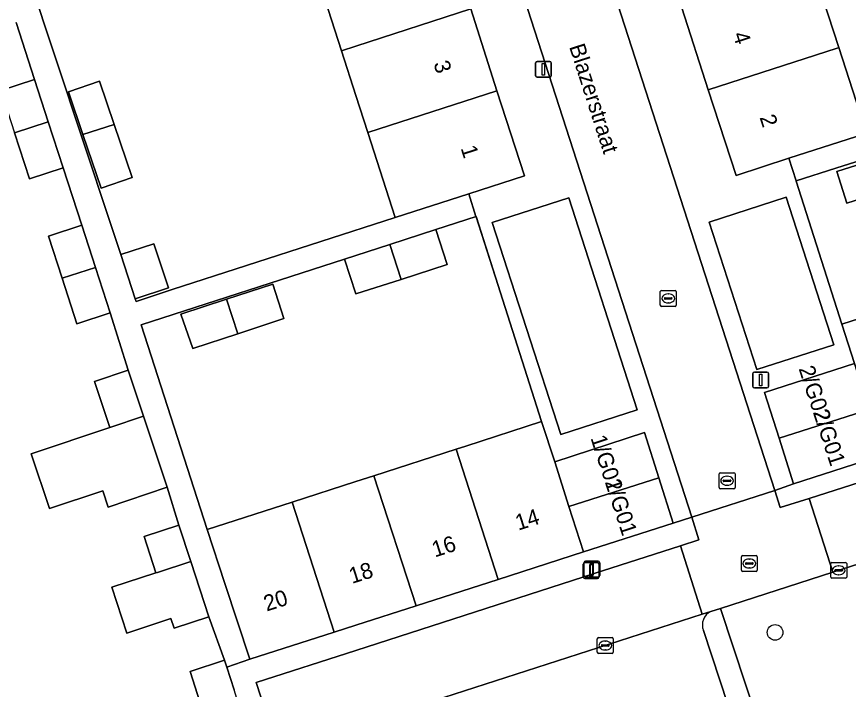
# Model space of a CAD drawing. Extents: x 159371 to 159986, y 382987 to 383597.
# Drawn here: x 159478.7 to 159530.9, y 383198.2 to 383240.4 of the extents above; entities that cross this region are included whole.
import ezdxf

# ---------------------------------------------------------------- set-up
doc = ezdxf.new("R2010")
doc.units = 0
for name, color, linetype in [('IMGEO_Boom', 7, 'Continuous'), ('IMGEO_Erf', 7, 'Continuous'), ('IMGEO_Groenvoorziening', 7, 'Continuous'), ('IMGEO_Kolk', 7, 'Continuous'), ('IMGEO_Lichtmast', 7, 'Continuous'), ('IMGEO_Muur', 7, 'Continuous'), ('IMGEO_Openbare_ruimte_label', 7, 'Continuous'), ('IMGEO_Pand', 7, 'Continuous'), ('IMGEO_Pand_nummerreeks', 7, 'Continuous'), ('IMGEO_Parkeervlak_open', 7, 'Continuous'), ('IMGEO_Rijbaan_lokaal_open', 7, 'Continuous'), ('IMGEO_Rioolput', 7, 'Continuous'), ('IMGEO_Voetpad_open', 7, 'Continuous')]:
    doc.layers.add(name, color=color, linetype=linetype)

msp = doc.modelspace()

# ---------------------------------------------------------------- linework, layer by layer
at = {"layer": 'IMGEO_Boom'}
msp.add_circle((159526.293, 383201.78), 0.489, dxfattribs=at)
at = {"layer": 'IMGEO_Erf'}
for points in [[(159531.284, 383283.727), (159529.246, 383283.829), (159519.728, 383280.725), (159521.455, 383275.325), (159518.605, 383274.414), (159520.255, 383269.333), (159521.919, 383264.211), (159523.611, 383259.001), (159525.285, 383253.847), (159526.535, 383250), (159526.957, 383248.702), (159528.622, 383243.576), (159530.29, 383238.439), (159532.035, 383233.068)], [(159474.303, 383258.392), (159484.606, 383227.42), (159485.248, 383225.462), (159487.33, 383226.144), (159488.238, 383223.375), (159486.157, 383222.692), (159486.209, 383222.532), (159488.475, 383223.275), (159502.462, 383227.783), (159500.748, 383233.11), (159500, 383235.437), (159499.1, 383238.237), (159497.445, 383243.381), (159495.793, 383248.517), (159495.316, 383250), (159494.126, 383253.699), (159492.462, 383258.873), (159488.591, 383257.619), (159486.93, 383262.784), (159490.801, 383264.037), (159489.146, 383269.183), (159485.21, 383267.909), (159483.482, 383273.28), (159466.224, 383267.732)], [(159477.72, 383235.751), (159479.834, 383236.442), (159478.696, 383240.003)], [(159490.525, 383196.453), (159489.601, 383199.327), (159491.758, 383200.033), (159490.78, 383202.765), (159488.592, 383202.046), (159488.395, 383202.646), (159485.637, 383201.74), (159484.695, 383204.606), (159487.453, 383205.513), (159486.706, 383207.787), (159488.894, 383208.506), (159488.161, 383210.876), (159484.461, 383209.638), (159484.12, 383210.655), (159480.784, 383209.538), (159479.633, 383212.974), (159484.57, 383214.627), (159483.604, 383217.513), (159485.703, 383218.216), (159484.587, 383221.813), (159482.497, 383221.131), (159481.567, 383223.976), (159480.704, 383226.615), (159482.795, 383227.299), (159481.642, 383230.906), (159479.529, 383230.216), (159478.586, 383233.1)]]:
    msp.add_lwpolyline(points, dxfattribs=at)
for points in [[(159561.744, 383231.135), (159558.829, 383240.129), (159535.859, 383232.707), (159532.941, 383231.781), (159530.104, 383230.88), (159527.615, 383230.086), (159527.624, 383230.058), (159530.484, 383221.094), (159535.245, 383222.623), (159535.829, 383222.811), (159541.002, 383224.472), (159546.128, 383226.119), (159551.293, 383227.778), (159556.447, 383229.434)], [(159485.967, 383230.29), (159484.01, 383229.627), (159482.871, 383232.987), (159481.96, 383235.674), (159483.917, 383236.337), (159484.837, 383233.623)], [(159530.8, 383228.688), (159530.169, 383230.674), (159533.007, 383231.575), (159535.925, 383232.502), (159536.566, 383230.519), (159533.646, 383229.592)], [(159507.534, 383227.84), (159505.016, 383227.034), (159505.723, 383224.846), (159502.835, 383223.911), (159500, 383222.994), (159499.277, 383225.177), (159486.536, 383221.053), (159490.664, 383208.234), (159495.999, 383209.952), (159500, 383211.241), (159501.129, 383211.604), (159506.286, 383213.265), (159506.889, 383213.459), (159511.648, 383214.991)], [(159491.878, 383222.663), (159494.778, 383223.614), (159495.481, 383221.446), (159492.581, 383220.495), (159489.763, 383219.571), (159489.015, 383221.724)]]:
    msp.add_lwpolyline(points, close=True, dxfattribs=at)
at = {"layer": 'IMGEO_Groenvoorziening'}
msp.add_lwpolyline([(159540.074, 383208.824), (159529.915, 383205.553), (159522.871, 383203.285), (159524.456, 383198.471), (159526.041, 383193.657), (159534.778, 383196.457), (159541.549, 383198.628), (159543.216, 383199.162), (159541.645, 383203.993)], close=True, dxfattribs=at)
at = {"layer": 'IMGEO_Kolk'}
for p, q in [((159519.095, 383222.288), (159519.095, 383223.14)), ((159519.17, 383223.214), (159520.022, 383223.214)), ((159519.583, 383222.994), (159519.608, 383222.994)), ((159520.096, 383223.14), (159520.096, 383222.288)), ((159519.354, 383222.708), (159519.354, 383222.72)), ((159519.792, 383222.671), (159519.394, 383222.671)), ((159519.397, 383222.757), (159519.795, 383222.757)), ((159519.838, 383222.72), (159519.838, 383222.708)), ((159520.022, 383222.214), (159519.17, 383222.214)), ((159519.606, 383222.434), (159519.581, 383222.434)), ((159522.783, 383210.86), (159522.783, 383211.712)), ((159522.858, 383211.786), (159523.71, 383211.786)), ((159523.271, 383211.566), (159523.296, 383211.566)), ((159523.784, 383211.712), (159523.784, 383210.86)), ((159523.042, 383211.28), (159523.042, 383211.292)), ((159523.48, 383211.243), (159523.082, 383211.243)), ((159523.085, 383211.329), (159523.483, 383211.329)), ((159523.294, 383211.006), (159523.269, 383211.006)), ((159523.526, 383211.292), (159523.526, 383211.28)), ((159523.71, 383210.786), (159522.858, 383210.786)), ((159529.785, 383205.245), (159529.785, 383206.097)), ((159529.86, 383206.171), (159530.712, 383206.171)), ((159530.273, 383205.951), (159530.298, 383205.951)), ((159530.786, 383206.097), (159530.786, 383205.245)), ((159530.044, 383205.665), (159530.044, 383205.677)), ((159530.482, 383205.628), (159530.084, 383205.628)), ((159530.087, 383205.714), (159530.485, 383205.714)), ((159530.296, 383205.391), (159530.271, 383205.391)), ((159530.528, 383205.677), (159530.528, 383205.665)), ((159530.712, 383205.171), (159529.86, 383205.171)), ((159515.143, 383200.531), (159515.143, 383201.383)), ((159515.218, 383201.457), (159516.07, 383201.457)), ((159515.631, 383201.237), (159515.656, 383201.237)), ((159516.144, 383201.383), (159516.144, 383200.531)), ((159515.402, 383200.951), (159515.402, 383200.963)), ((159515.84, 383200.914), (159515.442, 383200.914)), ((159515.445, 383201), (159515.843, 383201)), ((159515.654, 383200.677), (159515.629, 383200.677)), ((159515.886, 383200.963), (159515.886, 383200.951)), ((159516.07, 383200.457), (159515.218, 383200.457))]:
    msp.add_line(p, q, dxfattribs=at)
for points in [[(159519.095, 383222.288), (159519.095, 383223.14)], [(159519.17, 383223.214), (159520.022, 383223.214)], [(159520.096, 383223.14), (159520.096, 383222.288)], [(159520.022, 383222.214), (159519.17, 383222.214)], [(159522.783, 383210.86), (159522.783, 383211.712)], [(159522.858, 383211.786), (159523.71, 383211.786)], [(159523.784, 383211.712), (159523.784, 383210.86)], [(159523.71, 383210.786), (159522.858, 383210.786)], [(159529.785, 383205.245), (159529.785, 383206.097)], [(159529.86, 383206.171), (159530.712, 383206.171)], [(159530.786, 383206.097), (159530.786, 383205.245)], [(159530.712, 383205.171), (159529.86, 383205.171)], [(159515.143, 383200.531), (159515.143, 383201.383)], [(159515.218, 383201.457), (159516.07, 383201.457)], [(159516.144, 383201.383), (159516.144, 383200.531)], [(159516.07, 383200.457), (159515.218, 383200.457)]]:
    msp.add_lwpolyline(points, dxfattribs=at)
for centre, radius, start, end in [((159519.172, 383223.138), 0.0765, 91.552, 178.448), ((159519.172, 383223.138), 0.0765, 91.552, 178.448), ((159520.02, 383223.138), 0.0765, 1.552, 88.448), ((159520.02, 383223.138), 0.0765, 1.552, 88.448), ((159519.394, 383222.717), 0.0403, 85.8775, 175.7526), ((159519.391, 383222.707), 0.0366, 178.938, 274.7102), ((159519.795, 383222.714), 0.043, 264.8664, 352.4533), ((159519.799, 383222.719), 0.0386, 1.7309, 96.639), ((159519.172, 383222.29), 0.0765, 181.552, 268.448), ((159519.172, 383222.29), 0.0765, 181.552, 268.448), ((159520.02, 383222.29), 0.0765, 271.552, 358.448), ((159520.02, 383222.29), 0.0765, 271.552, 358.448), ((159522.86, 383211.71), 0.0765, 91.552, 178.448), ((159522.86, 383211.71), 0.0765, 91.552, 178.448), ((159523.708, 383211.71), 0.0765, 1.552, 88.448), ((159523.708, 383211.71), 0.0765, 1.552, 88.448), ((159523.082, 383211.289), 0.0403, 85.8775, 175.7526), ((159523.079, 383211.279), 0.0366, 178.938, 274.7102), ((159523.483, 383211.286), 0.043, 264.8664, 352.4533), ((159523.487, 383211.291), 0.0386, 1.7309, 96.639), ((159522.86, 383210.862), 0.0765, 181.552, 268.448), ((159522.86, 383210.862), 0.0765, 181.552, 268.448), ((159523.708, 383210.862), 0.0765, 271.552, 358.448), ((159523.708, 383210.862), 0.0765, 271.552, 358.448), ((159529.862, 383206.095), 0.0765, 91.552, 178.448), ((159529.862, 383206.095), 0.0765, 91.552, 178.448), ((159530.71, 383206.095), 0.0765, 1.552, 88.448), ((159530.71, 383206.095), 0.0765, 1.552, 88.448), ((159529.862, 383205.247), 0.0765, 181.552, 268.448), ((159529.862, 383205.247), 0.0765, 181.552, 268.448), ((159530.084, 383205.674), 0.0403, 85.8775, 175.7526), ((159530.081, 383205.664), 0.0366, 178.938, 274.7102), ((159530.485, 383205.671), 0.043, 264.8664, 352.4533), ((159530.489, 383205.676), 0.0386, 1.7309, 96.639), ((159530.71, 383205.247), 0.0765, 271.552, 358.448), ((159530.71, 383205.247), 0.0765, 271.552, 358.448), ((159515.22, 383201.381), 0.0765, 91.552, 178.448), ((159515.22, 383201.381), 0.0765, 91.552, 178.448), ((159516.068, 383201.381), 0.0765, 1.552, 88.448), ((159516.068, 383201.381), 0.0765, 1.552, 88.448), ((159515.22, 383200.533), 0.0765, 181.552, 268.448), ((159515.22, 383200.533), 0.0765, 181.552, 268.448), ((159515.442, 383200.96), 0.0403, 85.8775, 175.7526), ((159515.439, 383200.95), 0.0366, 178.938, 274.7102), ((159515.843, 383200.957), 0.043, 264.8664, 352.4533), ((159515.847, 383200.962), 0.0386, 1.7309, 96.639), ((159516.068, 383200.533), 0.0765, 271.552, 358.448), ((159516.068, 383200.533), 0.0765, 271.552, 358.448)]:
    msp.add_arc(centre, radius, start, end, dxfattribs=at)
for centre, major_axis, ratio, start_param, end_param in [((159519.582, 383222.714), (-0.387, 0.002), 0.722429, 4.712389, 7.853982), ((159519.607, 383222.714), (-0.39, 0.002), 0.717154, 1.570796, 4.712389), ((159523.27, 383211.286), (-0.387, 0.002), 0.722429, 4.712389, 7.853982), ((159523.295, 383211.286), (-0.39, 0.002), 0.717154, 1.570796, 4.712389), ((159530.272, 383205.671), (-0.387, 0.002), 0.722429, 4.712389, 7.853982), ((159530.297, 383205.671), (-0.39, 0.002), 0.717154, 1.570796, 4.712389), ((159515.63, 383200.957), (-0.387, 0.002), 0.722429, 4.712389, 7.853982), ((159515.655, 383200.957), (-0.39, 0.002), 0.717154, 1.570796, 4.712389)]:
    msp.add_ellipse(centre, major_axis=major_axis, ratio=ratio, start_param=start_param, end_param=end_param, dxfattribs=at)
at = {"layer": 'IMGEO_Lichtmast'}
for p, q in [((159511.268, 383236.674), (159511.268, 383237.474)), ((159511.268, 383237.474), (159511.268, 383236.674)), ((159511.368, 383237.574), (159512.158, 383237.574)), ((159512.158, 383237.574), (159511.368, 383237.574)), ((159512.258, 383237.474), (159512.258, 383236.674)), ((159512.258, 383236.674), (159512.258, 383237.474)), ((159512.158, 383236.574), (159511.368, 383236.574)), ((159511.368, 383236.574), (159512.158, 383236.574)), ((159524.893, 383217.202), (159524.893, 383218.002)), ((159524.893, 383218.002), (159524.893, 383217.202)), ((159524.993, 383218.102), (159525.783, 383218.102)), ((159525.783, 383218.102), (159524.993, 383218.102)), ((159525.883, 383218.002), (159525.883, 383217.202)), ((159525.883, 383217.202), (159525.883, 383218.002)), ((159525.783, 383217.102), (159524.993, 383217.102)), ((159524.993, 383217.102), (159525.783, 383217.102)), ((159514.263, 383205.253), (159514.263, 383206.053)), ((159514.263, 383206.053), (159514.263, 383205.253)), ((159514.305, 383205.344), (159514.305, 383206.144)), ((159514.305, 383206.144), (159514.305, 383205.344)), ((159514.363, 383206.153), (159515.153, 383206.153)), ((159515.153, 383206.153), (159514.363, 383206.153)), ((159514.405, 383206.244), (159515.195, 383206.244)), ((159515.195, 383206.244), (159514.405, 383206.244)), ((159515.253, 383206.053), (159515.253, 383205.253)), ((159515.253, 383205.253), (159515.253, 383206.053)), ((159515.295, 383206.144), (159515.295, 383205.344)), ((159515.295, 383205.344), (159515.295, 383206.144)), ((159515.195, 383205.244), (159514.405, 383205.244)), ((159514.405, 383205.244), (159515.195, 383205.244)), ((159515.153, 383205.153), (159514.363, 383205.153)), ((159514.363, 383205.153), (159515.153, 383205.153))]:
    msp.add_line(p, q, dxfattribs=at)
for points in [[(159511.688, 383237.449), (159511.838, 383237.449), (159511.838, 383236.699), (159511.688, 383236.699), (159511.688, 383237.449)], [(159525.313, 383217.977), (159525.463, 383217.977), (159525.463, 383217.227), (159525.313, 383217.227), (159525.313, 383217.977)], [(159514.683, 383206.028), (159514.833, 383206.028), (159514.833, 383205.278), (159514.683, 383205.278), (159514.683, 383206.028)], [(159514.725, 383206.119), (159514.875, 383206.119), (159514.875, 383205.369), (159514.725, 383205.369), (159514.725, 383206.119)]]:
    msp.add_lwpolyline(points, dxfattribs=at)
for centre, start, end in [((159511.368, 383237.474), 90, 180), ((159511.368, 383237.474), 90, 180), ((159512.158, 383237.474), 0, 90), ((159512.158, 383237.474), 360, 90), ((159511.368, 383236.674), 180, 270), ((159511.368, 383236.674), 180, 270), ((159512.158, 383236.674), 270, 0), ((159512.158, 383236.674), 270, 0), ((159524.993, 383218.002), 90, 180), ((159524.993, 383218.002), 90, 180), ((159525.783, 383218.002), 0, 90), ((159525.783, 383218.002), 360, 90), ((159524.993, 383217.202), 180, 270), ((159524.993, 383217.202), 180, 270), ((159525.783, 383217.202), 270, 0), ((159525.783, 383217.202), 270, 0), ((159514.363, 383206.053), 90, 180), ((159514.363, 383206.053), 90, 180), ((159514.405, 383206.144), 90, 180), ((159514.405, 383206.144), 90, 180), ((159515.153, 383206.053), 0, 90), ((159515.153, 383206.053), 360, 90), ((159515.195, 383206.144), 0, 90), ((159515.195, 383206.144), 360, 90), ((159514.363, 383205.253), 180, 270), ((159514.363, 383205.253), 180, 270), ((159514.405, 383205.344), 180, 270), ((159514.405, 383205.344), 180, 270), ((159515.153, 383205.253), 270, 0), ((159515.153, 383205.253), 270, 0), ((159515.195, 383205.344), 270, 0), ((159515.195, 383205.344), 270, 0)]:
    msp.add_arc(centre, 0.1, start, end, dxfattribs=at)
at = {"layer": 'IMGEO_Muur'}
for points in [[(159527.624, 383230.058), (159530.484, 383221.094)], [(159507.531, 383227.848), (159511.648, 383214.991)]]:
    msp.add_lwpolyline(points, dxfattribs=at)
at = {"layer": 'IMGEO_Pand'}
for points in [[(159505.546, 383246.004), (159500, 383244.208), (159497.445, 383243.381), (159499.1, 383238.237), (159500, 383238.528), (159507.201, 383240.86)], [(159528.622, 383243.576), (159520.441, 383240.921), (159522.107, 383235.784), (159530.19, 383238.407), (159530.29, 383238.439)], [(159507.201, 383240.86), (159500, 383238.528), (159499.1, 383238.237), (159500, 383235.437), (159500.748, 383233.11), (159508.849, 383235.734)], [(159522.107, 383235.784), (159523.844, 383230.429), (159527.161, 383231.498), (159531.921, 383233.031), (159532.035, 383233.068), (159530.29, 383238.439), (159530.19, 383238.407)], [(159479.834, 383236.442), (159477.72, 383235.751), (159478.586, 383233.1), (159480.701, 383233.786)], [(159484.837, 383233.623), (159483.917, 383236.337), (159481.96, 383235.674), (159482.871, 383232.987)], [(159500.748, 383233.11), (159502.462, 383227.783), (159507.076, 383229.267), (159510.568, 383230.39), (159508.849, 383235.734)], [(159480.701, 383233.786), (159478.586, 383233.1), (159479.529, 383230.216), (159481.642, 383230.906)], [(159484.837, 383233.623), (159482.871, 383232.987), (159484.01, 383229.627), (159485.967, 383230.29)], [(159533.007, 383231.575), (159530.169, 383230.674), (159530.8, 383228.688), (159533.646, 383229.592)], [(159482.795, 383227.299), (159480.704, 383226.615), (159481.567, 383223.976), (159483.659, 383224.654)], [(159502.835, 383223.911), (159505.723, 383224.846), (159505.016, 383227.034), (159502.126, 383226.099)], [(159485.248, 383225.462), (159486.157, 383222.692), (159488.238, 383223.375), (159487.33, 383226.144)], [(159502.835, 383223.911), (159502.126, 383226.099), (159500, 383225.411), (159499.277, 383225.177), (159500, 383222.994)], [(159483.659, 383224.654), (159481.567, 383223.976), (159482.497, 383221.131), (159484.587, 383221.813)], [(159491.878, 383222.663), (159492.581, 383220.495), (159495.481, 383221.446), (159494.778, 383223.614)], [(159491.878, 383222.663), (159489.015, 383221.724), (159489.763, 383219.571), (159492.581, 383220.495)], [(159531.277, 383218.64), (159532.194, 383215.748), (159533.093, 383212.915), (159538.46, 383214.64), (159535.829, 383222.811), (159535.245, 383222.623), (159530.484, 383221.094)], [(159531.277, 383218.64), (159525.641, 383216.827), (159526.549, 383213.96), (159532.194, 383215.748)], [(159484.57, 383214.627), (159486.67, 383215.33), (159485.703, 383218.216), (159483.604, 383217.513)], [(159526.549, 383213.96), (159527.457, 383211.093), (159533.093, 383212.915), (159532.194, 383215.748)], [(159486.67, 383215.33), (159484.57, 383214.627), (159479.633, 383212.974), (159480.784, 383209.538), (159484.12, 383210.655), (159484.461, 383209.638), (159488.161, 383210.876)], [(159508.931, 383205.106), (159514.272, 383206.822), (159513.353, 383209.671), (159512.481, 383212.472), (159511.648, 383214.991), (159506.889, 383213.459), (159506.286, 383213.265)], [(159519, 383211.469), (159518.096, 383214.307), (159512.481, 383212.472), (159513.353, 383209.671)], [(159508.931, 383205.106), (159506.286, 383213.265), (159501.129, 383211.604), (159503.773, 383203.448)], [(159495.999, 383209.952), (159498.642, 383201.8), (159500, 383202.236), (159503.773, 383203.448), (159501.129, 383211.604), (159500, 383211.241)], [(159519, 383211.469), (159513.353, 383209.671), (159514.272, 383206.822), (159519.903, 383208.631)], [(159495.999, 383209.952), (159490.664, 383208.234), (159491.778, 383204.846), (159493.339, 383200.096), (159498.642, 383201.8)], [(159487.453, 383205.513), (159487.545, 383205.542), (159489.641, 383206.231), (159488.894, 383208.506), (159486.706, 383207.787)], [(159489.641, 383206.231), (159487.545, 383205.542), (159487.453, 383205.513), (159484.695, 383204.606), (159485.637, 383201.74), (159488.395, 383202.646), (159488.592, 383202.046), (159490.78, 383202.765)], [(159492.685, 383197.153), (159492.353, 383198.185), (159491.9, 383199.592), (159491.758, 383200.033), (159489.601, 383199.327), (159490.525, 383196.453)]]:
    msp.add_lwpolyline(points, close=True, dxfattribs=at)
at = {"layer": 'IMGEO_Parkeervlak_open'}
for points in [[(159512.855, 383214.184), (159517.648, 383215.74), (159513.361, 383229.025), (159508.555, 383227.471)], [(159525.147, 383218.255), (159529.979, 383219.803), (159526.996, 383229.056), (159522.162, 383227.492)]]:
    msp.add_lwpolyline(points, close=True, dxfattribs=at)
for points in [[(159522.265, 383203.09), (159521.723, 383202.915), (159502.276, 383196.654), (159505.416, 383187.046), (159525.324, 383193.428)], [(159524.356, 383194.142), (159521.805, 383201.89)]]:
    msp.add_lwpolyline(points, dxfattribs=at)
msp.add_arc((159522.662, 383202.25), 0.929, 115.2802, 202.7728, dxfattribs=at)
at = {"layer": 'IMGEO_Rijbaan_lokaal_open'}
for points in [[(159521.064, 383209.004), (159526.269, 383210.676), (159514.229, 383247.954), (159509.028, 383246.282)], [(159520.354, 383207.214), (159521.723, 383202.915), (159522.265, 383203.09), (159522.871, 383203.285), (159529.915, 383205.553), (159528.425, 383210.177), (159526.617, 383209.599), (159526.269, 383210.676), (159521.064, 383209.004), (159521.521, 383207.59)]]:
    msp.add_lwpolyline(points, close=True, dxfattribs=at)
for points in [[(159591.243, 383219.067), (159572.368, 383213.005), (159570.5, 383218.852), (159566.151, 383217.448), (159564.747, 383221.794), (159528.425, 383210.177), (159529.915, 383205.553), (159540.074, 383208.824), (159540.707, 383209.028), (159559.015, 383214.923), (159559.453, 383215.064)], [(159501.85, 383196.521), (159502.276, 383196.654), (159521.723, 383202.915), (159520.354, 383207.214), (159514.946, 383205.47), (159500, 383200.651), (159493.749, 383198.635), (159499.75, 383180.18), (159500, 383180.243), (159536.251, 383191.843), (159534.778, 383196.457), (159526.041, 383193.657), (159525.324, 383193.428), (159505.416, 383187.046), (159504.961, 383186.9)]]:
    msp.add_lwpolyline(points, dxfattribs=at)
at = {"layer": 'IMGEO_Rioolput'}
for p, q in [((159524.178, 383205.672), (159524.178, 383206.524)), ((159524.253, 383206.598), (159525.105, 383206.598)), ((159524.666, 383206.378), (159524.691, 383206.378)), ((159525.179, 383206.524), (159525.179, 383205.672)), ((159524.437, 383206.092), (159524.437, 383206.104)), ((159524.875, 383206.055), (159524.477, 383206.055)), ((159524.48, 383206.141), (159524.878, 383206.141)), ((159524.689, 383205.818), (159524.664, 383205.818)), ((159524.921, 383206.104), (159524.921, 383206.092)), ((159525.105, 383205.598), (159524.253, 383205.598))]:
    msp.add_line(p, q, dxfattribs=at)
for points in [[(159524.178, 383205.672), (159524.178, 383206.524)], [(159524.253, 383206.598), (159525.105, 383206.598)], [(159525.179, 383206.524), (159525.179, 383205.672)], [(159525.105, 383205.598), (159524.253, 383205.598)]]:
    msp.add_lwpolyline(points, dxfattribs=at)
for centre, radius, start, end in [((159524.255, 383206.522), 0.0765, 91.552, 178.448), ((159524.255, 383206.522), 0.0765, 91.552, 178.448), ((159525.103, 383206.522), 0.0765, 1.552, 88.448), ((159525.103, 383206.522), 0.0765, 1.552, 88.448), ((159524.477, 383206.101), 0.0403, 85.8775, 175.7526), ((159524.474, 383206.091), 0.0366, 178.938, 274.7102), ((159524.878, 383206.098), 0.043, 264.8664, 352.4533), ((159524.882, 383206.103), 0.0386, 1.7309, 96.639), ((159524.255, 383205.674), 0.0765, 181.552, 268.448), ((159524.255, 383205.674), 0.0765, 181.552, 268.448), ((159525.103, 383205.674), 0.0765, 271.552, 358.448), ((159525.103, 383205.674), 0.0765, 271.552, 358.448)]:
    msp.add_arc(centre, radius, start, end, dxfattribs=at)
for centre, major_axis, ratio, start_param, end_param in [((159524.665, 383206.098), (-0.387, 0.002), 0.722429, 4.712389, 7.853982), ((159524.69, 383206.098), (-0.39, 0.002), 0.717154, 1.570796, 4.712389)]:
    msp.add_ellipse(centre, major_axis=major_axis, ratio=ratio, start_param=start_param, end_param=end_param, dxfattribs=at)
at = {"layer": 'IMGEO_Voetpad_open'}
for points in [[(159505.455, 383275.111), (159505.614, 383274.618), (159506.466, 383271.982), (159512.938, 383251.951), (159513.568, 383250), (159514.229, 383247.954), (159526.269, 383210.676), (159527.457, 383211.093), (159526.549, 383213.96), (159525.641, 383216.827), (159531.277, 383218.64), (159530.484, 383221.094), (159527.624, 383230.058), (159527.615, 383230.086), (159527.161, 383231.498), (159523.844, 383230.429), (159522.107, 383235.784), (159520.441, 383240.921)], [(159478.696, 383240.003), (159479.834, 383236.442), (159480.701, 383233.786), (159481.642, 383230.906), (159482.795, 383227.299), (159483.659, 383224.654), (159484.587, 383221.813), (159485.703, 383218.216), (159486.67, 383215.33), (159488.161, 383210.876), (159488.894, 383208.506), (159489.641, 383206.231), (159490.78, 383202.765), (159491.758, 383200.033), (159491.9, 383199.592), (159493.339, 383200.096), (159491.778, 383204.846), (159490.664, 383208.234), (159486.536, 383221.053), (159499.277, 383225.177), (159500, 383225.411), (159502.126, 383226.099), (159505.016, 383227.034), (159507.534, 383227.84), (159507.531, 383227.848), (159507.076, 383229.267), (159502.462, 383227.783), (159488.475, 383223.275), (159486.209, 383222.532), (159486.157, 383222.692), (159485.248, 383225.462), (159484.606, 383227.42), (159474.303, 383258.392)], [(159507.201, 383240.86), (159508.849, 383235.734), (159510.568, 383230.39), (159507.076, 383229.267), (159507.531, 383227.848), (159507.534, 383227.84), (159511.648, 383214.991), (159512.481, 383212.472), (159518.096, 383214.307), (159519, 383211.469), (159519.903, 383208.631), (159521.064, 383209.004), (159509.028, 383246.282)], [(159531.921, 383233.031), (159527.161, 383231.498), (159527.615, 383230.086), (159530.104, 383230.88), (159532.941, 383231.781)], [(159591.966, 383222.185), (159589.114, 383221.244), (159586.261, 383220.303), (159584.434, 383225.871), (159581.974, 383225.106), (159571.447, 383221.705), (159566.861, 383220.219), (159565.818, 383223.436), (159564.388, 383222.975), (159559.076, 383221.267), (159553.922, 383219.611), (159548.758, 383217.951), (159543.632, 383216.303), (159538.46, 383214.64), (159533.093, 383212.915), (159527.457, 383211.093), (159526.269, 383210.676), (159526.617, 383209.599), (159528.425, 383210.177), (159564.747, 383221.794), (159566.151, 383217.448), (159570.5, 383218.852), (159572.368, 383213.005), (159591.243, 383219.067)], [(159499.75, 383180.18), (159493.749, 383198.635), (159500, 383200.651), (159514.946, 383205.47), (159520.354, 383207.214), (159521.521, 383207.59), (159521.064, 383209.004), (159519.903, 383208.631), (159514.272, 383206.822), (159508.931, 383205.106), (159503.773, 383203.448), (159500, 383202.236), (159498.642, 383201.8), (159493.339, 383200.096), (159491.9, 383199.592), (159492.353, 383198.185)], [(159525.324, 383193.428), (159526.041, 383193.657), (159524.456, 383198.471), (159522.871, 383203.285), (159522.265, 383203.09)], [(159521.805, 383201.89), (159524.356, 383194.142)]]:
    msp.add_lwpolyline(points, dxfattribs=at)
for points in [[(159513.361, 383229.025), (159517.648, 383215.74), (159512.855, 383214.184), (159508.555, 383227.471)], [(159526.996, 383229.056), (159529.979, 383219.803), (159525.147, 383218.255), (159522.162, 383227.492)]]:
    msp.add_lwpolyline(points, close=True, dxfattribs=at)
msp.add_arc((159522.662, 383202.25), 0.929, 115.2802, 202.7728, dxfattribs=at)

# ---------------------------------------------------------------- texts
at = {"layer": 'IMGEO_Openbare_ruimte_label'}
msp.add_text('Blazerstraat', height=1, rotation=287.8734, dxfattribs=at).set_placement((159513.364, 383238.498))
at = {"layer": 'IMGEO_Pand_nummerreeks'}
for s, rotation, p in [('4', 287.9684, (159523.628, 383239.263)), ('3', 287.83, (159504.854, 383237.442)), ('2', 287.9684, (159525.313, 383234.069)), ('1', 287.83, (159506.561, 383232.137)), ('2/G02', 288.1595, (159527.761, 383218.317)), ('2/G01', 288.1595, (159528.654, 383215.593)), ('1/G02', 288.0247, (159514.706, 383213.971)), ('1/G01', 288.0247, (159515.6, 383211.225)), ('14', 17.8128, (159510.185, 383208.155)), ('16', 17.8128, (159504.952, 383206.474)), ('18', 17.7232, (159499.749, 383204.816)), ('20', 17.8128, (159494.401, 383203.084))]:
    msp.add_text(s, height=1, rotation=rotation, dxfattribs=at).set_placement(p)

doc.saveas('drawing.dxf')
